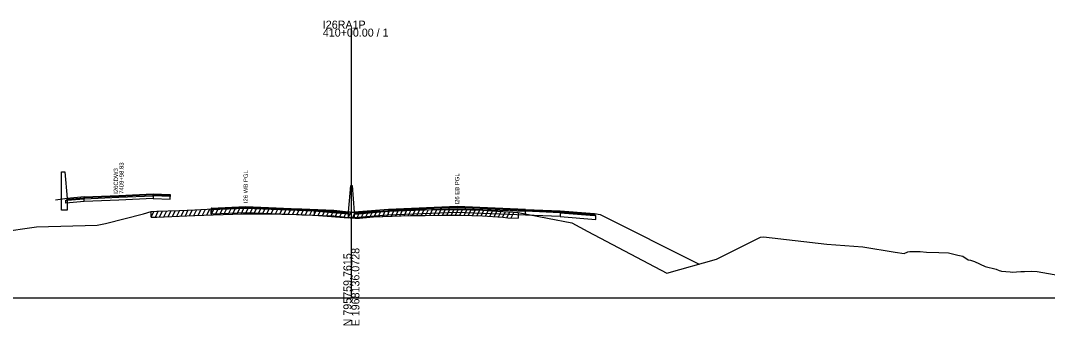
# Model space of a CAD drawing. Extents: x 1017 to 19997, y -1947 to 50737.
# Drawn here: x 16484.2 to 16843.5, y 9990.3 to 10097.1 of the extents above; entities that cross this region are included whole.
import ezdxf

# ---------------------------------------------------------------- set-up
doc = ezdxf.new("R2010")
doc.units = 0
for name, color, linetype in [('RD_GPK_XS_Cell', 7, 'Continuous'), ('RD_XS_Base', 7, 'Continuous'), ('RD_XS_ExGround', 7, 'Continuous'), ('RD_XS_ExPaveRet', 7, 'Continuous'), ('RD_XS_Greenside', 7, 'Continuous'), ('RD_XS_MedBWall', 7, 'Continuous'), ('RD_XS_Pave', 7, 'Continuous'), ('RD_XS_PaveOvlay', 7, 'Continuous'), ('RD_XS_TX_Notes', 7, 'Continuous')]:
    doc.layers.add(name, color=color, linetype=linetype)

msp = doc.modelspace()

# ---------------------------------------------------------------- linework, layer by layer
at = {"layer": 'RD_GPK_XS_Cell'}
for p, q in [((16600, 10000), (16600, 10094.29)), ((16000, 10000), (16600, 10000)), ((16600, 10000), (17200, 10000))]:
    msp.add_line(p, q, dxfattribs=at)
at = {"layer": 'RD_XS_Base'}
for points in [[(16530.6, 10035.73), (16530.6, 10034.73)], [(16536.61, 10034.5), (16536.61, 10035.5)], [(16500.03, 10034.15), (16500.53, 10034.19), (16506.54, 10034.7)], [(16500.03, 10033.15), (16500.03, 10034.15)], [(16506.54, 10033.7), (16500.03, 10033.15)], [(16530.6, 10034.73), (16518.57, 10034.21), (16506.54, 10033.7)], [(16506.54, 10033.7), (16506.54, 10034.7)], [(16530.6, 10034.73), (16536.61, 10034.5)], [(16550.95, 10029.43), (16550.95, 10030.77)], [(16551, 10029.43), (16550.95, 10029.43)], [(16551, 10030.77), (16551, 10029.43)], [(16551, 10029.43), (16563, 10029.92), (16587, 10028.96)], [(16599, 10029.35), (16587, 10030.3)], [(16587, 10030.3), (16587, 10028.96)], [(16587, 10028.96), (16599, 10028.01)], [(16599, 10028.01), (16599, 10029.35)], [(16601, 10028.01), (16601, 10029.35)], [(16613, 10028.96), (16601, 10028.01)], [(16613, 10028.96), (16613, 10030.3)], [(16660.95, 10028.96), (16637, 10029.92), (16613, 10028.96)], [(16660.95, 10028.96), (16660.95, 10030.3)], [(16673, 10028.48), (16660.95, 10028.96)], [(16673, 10029.82), (16673, 10028.48)], [(16685.5, 10028.82), (16685, 10028.86), (16673, 10029.82)], [(16673, 10028.48), (16685.5, 10027.48)], [(16685.5, 10027.48), (16685.5, 10028.82)]]:
    msp.add_lwpolyline(points, dxfattribs=at)
at = {"layer": 'RD_XS_ExGround'}
msp.add_lwpolyline([(16476.75, 10022.96), (16489.86, 10024.83), (16511.06, 10025.49), (16514.01, 10026.06), (16527.22, 10029.45), (16529.91, 10030.22), (16531.97, 10030.3), (16539.7, 10030.64), (16545.2, 10030.86), (16551.64, 10031.11), (16562.07, 10031.36), (16563.48, 10031.39), (16564.06, 10031.4), (16570.53, 10031.43), (16580.8, 10031.17), (16581.72, 10031.14), (16582.63, 10031.11), (16593.89, 10030.69), (16598.93, 10030.15), (16599.51, 10030.07), (16600, 10030.04), (16601.35, 10029.95), (16602.18, 10029.89), (16602.81, 10029.94), (16607.69, 10030.32), (16614.26, 10030.56), (16620.65, 10030.78), (16625.79, 10030.86), (16631.63, 10030.96), (16633.8, 10030.93), (16638.45, 10030.9), (16645.87, 10030.7), (16652.94, 10030.2), (16654.69, 10030.07), (16658.35, 10029.85), (16668.63, 10027.88), (16677.1, 10026.25), (16682.69, 10023.18), (16710.35, 10008.6), (16727.78, 10013.57), (16743.12, 10021.21), (16744.21, 10021.4), (16766.31, 10018.75), (16778.97, 10017.81), (16790.28, 10015.98), (16793.35, 10015.5), (16794.73, 10016.05), (16795.41, 10016.22), (16799.03, 10016.17), (16801.18, 10016.04), (16805.49, 10015.86), (16808.88, 10015.75), (16812.23, 10014.88), (16813.93, 10014.58), (16815.79, 10013.35), (16816.59, 10013.14), (16817.96, 10012.68), (16821.7, 10011.02), (16825.57, 10009.98), (16826.61, 10009.59), (16827.05, 10009.43), (16827.41, 10009.32), (16830.47, 10009.07), (16831.14, 10009.02), (16834.27, 10009.27), (16835.46, 10009.27), (16837.83, 10009.38), (16839.95, 10009.27), (16841.94, 10008.85), (16849.18, 10007.56)], dxfattribs=at)
at = {"layer": 'RD_XS_ExPaveRet'}
for p, q in [((16529.91, 10028.22), (16530.93, 10030.26)), ((16529.91, 10028.22), (16529.91, 10030.22)), ((16529.91, 10028.22), (16531.97, 10028.3)), ((16531.41, 10028.28), (16532.43, 10030.32)), ((16531.97, 10028.3), (16539.7, 10028.64)), ((16532.91, 10028.35), (16533.93, 10030.39)), ((16534.41, 10028.41), (16535.43, 10030.45)), ((16535.91, 10028.48), (16536.93, 10030.52)), ((16537.41, 10028.54), (16538.43, 10030.58)), ((16538.91, 10028.61), (16539.93, 10030.65)), ((16539.7, 10028.64), (16545.2, 10028.86)), ((16540.41, 10028.67), (16541.43, 10030.71)), ((16541.91, 10028.73), (16542.93, 10030.77)), ((16543.41, 10028.79), (16544.43, 10030.83)), ((16544.91, 10028.85), (16545.93, 10030.89)), ((16545.2, 10028.86), (16551.64, 10029.11)), ((16546.41, 10028.91), (16547.43, 10030.95)), ((16547.91, 10028.97), (16548.93, 10031.01)), ((16549.41, 10029.02), (16550.43, 10031.06)), ((16550.91, 10029.08), (16551.93, 10031.12)), ((16551.64, 10029.11), (16562.07, 10029.36)), ((16552.41, 10029.13), (16553.42, 10031.15)), ((16553.91, 10029.17), (16554.92, 10031.19)), ((16555.41, 10029.2), (16556.42, 10031.23)), ((16556.91, 10029.24), (16557.92, 10031.26)), ((16558.41, 10029.27), (16559.42, 10031.3)), ((16559.91, 10029.31), (16560.92, 10031.33)), ((16561.41, 10029.34), (16562.42, 10031.37)), ((16562.07, 10029.36), (16563.48, 10029.39)), ((16562.91, 10029.38), (16563.92, 10031.4)), ((16563.48, 10029.39), (16564.06, 10029.4)), ((16564.06, 10029.4), (16570.53, 10029.43)), ((16564.41, 10029.4), (16565.41, 10031.41)), ((16565.91, 10029.41), (16566.91, 10031.41)), ((16567.41, 10029.42), (16568.41, 10031.42)), ((16568.91, 10029.42), (16569.91, 10031.43)), ((16570.41, 10029.43), (16571.4, 10031.41)), ((16570.53, 10029.43), (16580.8, 10029.17)), ((16571.91, 10029.39), (16572.9, 10031.37)), ((16573.41, 10029.36), (16574.4, 10031.33)), ((16574.91, 10029.32), (16575.9, 10031.29)), ((16576.41, 10029.28), (16577.4, 10031.26)), ((16577.91, 10029.24), (16578.9, 10031.22)), ((16579.41, 10029.2), (16580.4, 10031.18)), ((16580.8, 10029.17), (16581.72, 10029.14)), ((16580.91, 10029.17), (16581.9, 10031.14)), ((16581.72, 10029.14), (16582.63, 10029.11)), ((16582.41, 10029.12), (16583.39, 10031.08)), ((16582.63, 10029.11), (16593.89, 10028.69)), ((16583.91, 10029.06), (16584.89, 10031.03)), ((16585.41, 10029.01), (16586.39, 10030.97)), ((16586.91, 10028.95), (16587.89, 10030.92)), ((16588.41, 10028.9), (16589.39, 10030.86)), ((16589.91, 10028.84), (16590.89, 10030.8)), ((16591.41, 10028.79), (16592.39, 10030.75)), ((16592.91, 10028.73), (16593.89, 10030.69)), ((16593.89, 10028.69), (16598.93, 10028.15)), ((16594.41, 10028.64), (16595.36, 10030.54)), ((16595.91, 10028.48), (16596.86, 10030.37)), ((16597.41, 10028.31), (16598.36, 10030.21)), ((16598.91, 10028.15), (16599.86, 10030.05)), ((16598.93, 10028.15), (16599.51, 10028.07)), ((16600.41, 10028.01), (16601.38, 10029.95)), ((16601.91, 10027.91), (16602.93, 10029.95)), ((16602.81, 10027.94), (16607.69, 10028.32)), ((16603.41, 10027.99), (16604.45, 10030.07)), ((16604.91, 10028.1), (16605.95, 10030.19)), ((16606.41, 10028.22), (16607.45, 10030.3)), ((16607.69, 10028.32), (16614.26, 10028.56)), ((16607.91, 10028.33), (16608.93, 10030.37)), ((16609.41, 10028.38), (16610.43, 10030.42)), ((16610.91, 10028.44), (16611.93, 10030.47)), ((16612.41, 10028.49), (16613.43, 10030.53)), ((16613.91, 10028.54), (16614.93, 10030.58)), ((16614.26, 10028.56), (16620.65, 10028.78)), ((16615.41, 10028.6), (16616.43, 10030.63)), ((16616.91, 10028.65), (16617.93, 10030.68)), ((16618.41, 10028.7), (16619.43, 10030.74)), ((16619.91, 10028.75), (16620.93, 10030.78)), ((16620.65, 10028.78), (16625.79, 10028.86)), ((16621.41, 10028.79), (16622.42, 10030.81)), ((16622.91, 10028.82), (16623.92, 10030.83)), ((16624.41, 10028.84), (16625.42, 10030.86)), ((16625.79, 10028.86), (16631.63, 10028.96)), ((16625.91, 10028.86), (16626.92, 10030.88)), ((16627.41, 10028.89), (16628.42, 10030.91)), ((16628.91, 10028.92), (16629.92, 10030.93)), ((16630.41, 10028.94), (16631.42, 10030.96)), ((16631.63, 10028.96), (16633.8, 10028.93)), ((16631.91, 10028.96), (16632.9, 10030.95)), ((16633.41, 10028.94), (16634.41, 10030.93)), ((16633.8, 10028.93), (16638.45, 10028.9)), ((16634.91, 10028.93), (16635.91, 10030.92)), ((16636.41, 10028.91), (16637.41, 10030.9)), ((16637.91, 10028.9), (16638.9, 10030.88)), ((16638.45, 10028.9), (16645.87, 10028.7)), ((16639.41, 10028.87), (16640.4, 10030.84)), ((16640.91, 10028.83), (16641.9, 10030.8)), ((16642.41, 10028.79), (16643.4, 10030.76)), ((16643.91, 10028.75), (16644.9, 10030.72)), ((16645.41, 10028.71), (16646.39, 10030.66)), ((16645.87, 10028.7), (16652.94, 10028.2)), ((16646.91, 10028.63), (16647.88, 10030.56)), ((16648.41, 10028.52), (16649.38, 10030.45)), ((16649.91, 10028.41), (16650.88, 10030.34)), ((16651.41, 10028.31), (16652.38, 10030.24)), ((16652.91, 10028.2), (16653.88, 10030.13)), ((16652.94, 10028.2), (16654.69, 10028.07)), ((16654.41, 10028.09), (16655.38, 10030.03)), ((16655.91, 10028), (16656.88, 10029.94)), ((16658.35, 10029.85), (16658.35, 10027.85)), ((16599.51, 10028.07), (16600, 10028.04)), ((16600, 10028.04), (16601.35, 10027.95)), ((16601.35, 10027.95), (16602.18, 10027.89)), ((16602.18, 10027.89), (16602.81, 10027.94)), ((16654.69, 10028.07), (16658.35, 10027.85))]:
    msp.add_line(p, q, dxfattribs=at)
at = {"layer": 'RD_XS_Greenside'}
for points in [[(16500.53, 10034.83), (16496.52, 10034.17)], [(16685, 10029.53), (16687, 10029.2)], [(16687, 10029.2), (16721.71, 10011.84)]]:
    msp.add_lwpolyline(points, dxfattribs=at)
at = {"layer": 'RD_XS_MedBWall'}
for points in [[(16498.53, 10030.68), (16498.53, 10044.17)], [(16498.53, 10044.17), (16499.78, 10044.17), (16500.53, 10034.83)], [(16599, 10030.01), (16599.75, 10039.35)], [(16599.75, 10039.35), (16600.25, 10039.35), (16601, 10030.01)], [(16500.53, 10034.83), (16500.53, 10030.68)], [(16500.53, 10030.68), (16498.53, 10030.68)], [(16599, 10028.01), (16599, 10029.35), (16599, 10030.01)], [(16601, 10030.01), (16601, 10029.35), (16601, 10028.01)], [(16601, 10028.01), (16599, 10028.01)]]:
    msp.add_lwpolyline(points, dxfattribs=at)
at = {"layer": 'RD_XS_Pave'}
for points in [[(16530.6, 10036.05), (16518.57, 10035.53), (16506.54, 10035.01)], [(16506.54, 10034.7), (16518.57, 10035.21), (16530.6, 10035.73)], [(16530.6, 10035.73), (16530.6, 10036.05)], [(16530.6, 10036.05), (16536.61, 10035.83)], [(16536.61, 10035.5), (16530.6, 10035.73)], [(16536.61, 10035.83), (16536.61, 10035.5)], [(16500.53, 10034.51), (16506.54, 10035.01)], [(16506.54, 10034.7), (16500.53, 10034.19)], [(16500.53, 10034.19), (16500.53, 10034.51)], [(16506.54, 10035.01), (16506.54, 10034.7)], [(16550.95, 10031.11), (16551, 10031.11)], [(16550.95, 10030.77), (16550.95, 10031.11)], [(16551, 10030.77), (16550.95, 10030.77)], [(16587, 10030.3), (16563, 10031.26), (16551, 10030.77)], [(16551, 10031.11), (16551, 10030.77)], [(16587, 10030.64), (16587, 10030.3)], [(16587, 10030.64), (16599, 10029.69)], [(16599, 10029.69), (16599, 10029.35)], [(16601, 10029.35), (16613, 10030.3)], [(16601, 10029.69), (16601, 10029.35)], [(16660.95, 10030.64), (16637, 10031.6), (16613, 10030.64)], [(16613, 10030.3), (16637, 10031.26), (16660.95, 10030.3)], [(16613, 10030.64), (16613, 10030.3)], [(16660.95, 10030.64), (16673, 10030.16)], [(16660.95, 10030.3), (16660.95, 10030.64)], [(16673, 10029.82), (16660.95, 10030.3)], [(16673, 10030.16), (16673, 10029.82)], [(16673, 10029.82), (16685, 10028.86)], [(16685, 10028.86), (16685, 10029.2)]]:
    msp.add_lwpolyline(points, dxfattribs=at)
at = {"layer": 'RD_XS_PaveOvlay'}
for points in [[(16506.54, 10035.33), (16500.53, 10034.83)], [(16506.54, 10035.33), (16518.57, 10035.85), (16530.6, 10036.37)], [(16506.54, 10035.01), (16506.54, 10035.33)], [(16530.6, 10036.37), (16530.6, 10036.05)], [(16530.6, 10036.37), (16536.61, 10036.15)], [(16536.61, 10036.15), (16536.61, 10035.83)], [(16500.53, 10034.83), (16500.53, 10034.51)], [(16551, 10031.45), (16563, 10031.93), (16587, 10030.97)], [(16660.95, 10030.97), (16637, 10031.93), (16613, 10030.97)], [(16551, 10031.45), (16550.95, 10031.45)], [(16550.95, 10031.45), (16550.95, 10031.11)], [(16587, 10030.64), (16563, 10031.6), (16551, 10031.11)], [(16551, 10031.11), (16551, 10031.45)], [(16587, 10030.97), (16587, 10030.64)], [(16587, 10030.97), (16599, 10030.01)], [(16599, 10030.01), (16599, 10029.69)], [(16613, 10030.97), (16601, 10030.01)], [(16601, 10029.69), (16613, 10030.64)], [(16601, 10030.01), (16601, 10029.69)], [(16613, 10030.64), (16613, 10030.97)], [(16660.95, 10030.97), (16673, 10030.49)], [(16660.95, 10030.64), (16660.95, 10030.97)], [(16673, 10030.49), (16685, 10029.53)], [(16673, 10030.16), (16673, 10030.49)], [(16685, 10029.2), (16673, 10030.16)], [(16685, 10029.53), (16685, 10029.2)]]:
    msp.add_lwpolyline(points, dxfattribs=at)

# ---------------------------------------------------------------- texts
at = {"layer": 'RD_GPK_XS_Cell'}
for s, p in [('I26RA1P', (16590, 10094.29)), ('410+00.00 / 1', (16590, 10091.49))]:
    msp.add_text(s, height=2.8, dxfattribs=at).set_placement(p)
for s, p in [('N 795759.7615', (16600, 9990)), ('E 1968136.0728', (16602.8, 9990))]:
    msp.add_text(s, height=2.8, rotation=90, dxfattribs=at).set_placement(p)
at = {"layer": 'RD_XS_TX_Notes'}
for s, p in [(' 7409+98.83', (16520.29, 10035.85)), (' I26CDW3', (16518.34, 10035.85)), ('I26 WB PGL', (16563.75, 10033.16)), ('I26 EB PGL', (16637.75, 10032.66))]:
    msp.add_text(s, height=1.5, rotation=90, dxfattribs=at).set_placement(p)

doc.saveas('drawing.dxf')
